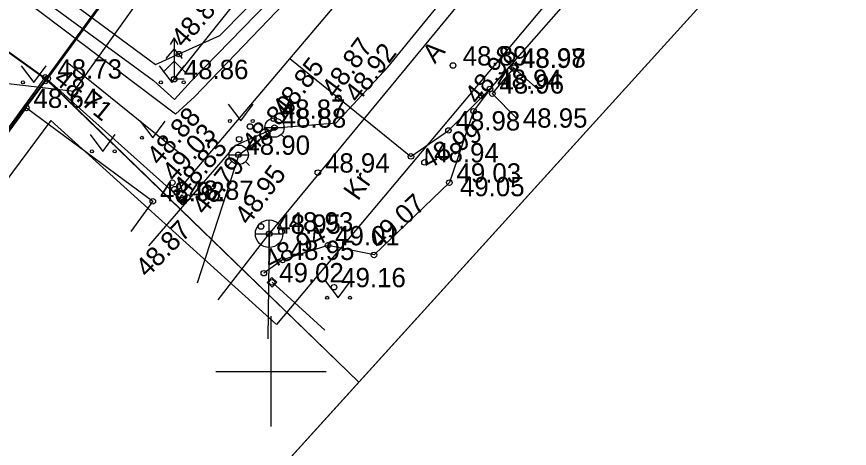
# Model space of a CAD drawing. Extents: x 640876 to 641418, y 6455595 to 6456085.
# Drawn here: x 641190.78 to 641220.97, y 6455847.21 to 6455862.86 of the extents above; entities that cross this region are included whole.
import ezdxf

# ---------------------------------------------------------------- set-up
doc = ezdxf.new("R2010")
doc.units = 0
for name, color, linetype in [('AED', 7, 'Continuous'), ('HALJASTUS', 7, 'Continuous'), ('HOONE', 7, 'Continuous'), ('KKAEV', 7, 'Continuous'), ('KORGUS', 7, 'Continuous'), ('KTRASS', 7, 'Continuous'), ('MOOTKORG', 7, 'Continuous'), ('MOOTMPUNKT', 7, 'Continuous'), ('MOOTPIIR', 7, 'Continuous'), ('PIIR', 7, 'Continuous'), ('PUU', 7, 'Continuous'), ('SITRASS', 7, 'Continuous'), ('TEE', 7, 'Continuous'), ('TTRASS', 7, 'Continuous'), ('VKAEV', 7, 'Continuous'), ('VORK', 7, 'Continuous'), ('VTRASS', 7, 'Continuous')]:
    doc.layers.add(name, color=color, linetype=linetype)

msp = doc.modelspace()

# ---------------------------------------------------------------- linework, layer by layer
at = {"layer": 'AED'}
for p, q in [((641208.634, 6455861.003), (641208.798, 6455861.191)), ((641208.798, 6455861.191), (641208.986, 6455861.027)), ((641208.634, 6455861.003), (641208.822, 6455860.839)), ((641208.822, 6455860.839), (641208.986, 6455861.027)), ((641196.764, 6455856.398), (641196.596, 6455856.212)), ((641196.596, 6455856.212), (641196.782, 6455856.044)), ((641196.764, 6455856.398), (641196.95, 6455856.23)), ((641196.95, 6455856.23), (641196.782, 6455856.044)), ((641200.03, 6455853.406), (641199.862, 6455853.22)), ((641199.862, 6455853.22), (641200.048, 6455853.052)), ((641200.03, 6455853.406), (641200.216, 6455853.238)), ((641200.216, 6455853.238), (641200.048, 6455853.052))]:
    msp.add_line(p, q, dxfattribs=at)
for points in [[(641208.8, 6455861.001), (641208.024, 6455860.071), (641208.909, 6455859.17)], [(641190.933, 6455807.239), (641184.916, 6455813.051), (641177.832, 6455819.82), (641173.204, 6455824.372), (641168.374, 6455829.07), (641172.424, 6455834.304), (641178.267, 6455842.112), (641182.222, 6455847.378), (641186.037, 6455852.714), (641191.816, 6455860.659), (641196.772, 6455856.219)], [(641201.952, 6455851.499), (641200.039, 6455853.229)]]:
    msp.add_lwpolyline(points, dxfattribs=at)
at = {"layer": 'HALJASTUS'}
for p, q in [((641190.945, 6455861.083), (641191.409, 6455860.477)), ((641191.409, 6455860.477), (641191.854, 6455861.083)), ((641195.945, 6455861.083), (641196.409, 6455860.477)), ((641196.409, 6455860.477), (641196.854, 6455861.083)), ((641198.448, 6455859.685), (641198.911, 6455859.078)), ((641198.911, 6455859.078), (641199.357, 6455859.685)), ((641195.26, 6455859.075), (641195.723, 6455858.468)), ((641195.723, 6455858.468), (641196.169, 6455859.075)), ((641193.445, 6455858.583), (641193.909, 6455857.977)), ((641193.909, 6455857.977), (641194.354, 6455858.583)), ((641201.976, 6455853.277), (641202.439, 6455852.67)), ((641202.439, 6455852.67), (641202.885, 6455853.277))]:
    msp.add_line(p, q, dxfattribs=at)
for centre in [(641191.008, 6455860.477), (641191.836, 6455860.477), (641196.008, 6455860.477), (641196.836, 6455860.477), (641198.51, 6455859.078), (641199.339, 6455859.078), (641195.322, 6455858.468), (641196.151, 6455858.468), (641193.508, 6455857.977), (641194.336, 6455857.977), (641202.038, 6455852.67), (641202.867, 6455852.67)]:
    msp.add_circle(centre, 0.055, dxfattribs=at)
at = {"layer": 'HOONE'}
msp.add_lwpolyline([(641179.081, 6455843.151), (641182.222, 6455847.378), (641191.132, 6455859.552), (641195.718, 6455856.166), (641194.92, 6455855.074)], dxfattribs=at)
msp.add_lwpolyline([(641179.081, 6455843.151), (641182.222, 6455847.378), (641191.132, 6455859.552), (641195.718, 6455856.166), (641194.92, 6455855.074)], dxfattribs=at)
at = {"layer": 'KKAEV'}
for p, q in [((641199.934, 6455854.49), (641199.934, 6455855.49)), ((641199.434, 6455854.99), (641200.434, 6455854.99))]:
    msp.add_line(p, q, dxfattribs=at)
msp.add_circle((641199.934, 6455854.99), 0.5, dxfattribs=at)
at = {"layer": 'KORGUS'}
for centre in [(641196.669, 6455861.503), (641206.602, 6455861.089), (641191.816, 6455860.659), (641191.907, 6455860.615), (641196.491, 6455860.595), (641202.442, 6455859.92), (641202.446, 6455859.883), (641207.634, 6455859.984), (641207.347, 6455859.432), (641199.241, 6455858.879), (641198.849, 6455858.417), (641205.074, 6455857.794), (641205.567, 6455857.577), (641201.699, 6455857.207), (641196.423, 6455856.841), (641196.5, 6455856.609), (641196.58, 6455856.487), (641196.837, 6455856.159), (641196.975, 6455856.303), (641199.641, 6455855.252), (641203.737, 6455854.222), (641199.742, 6455853.559)]:
    msp.add_circle(centre, 0.1, dxfattribs=at)
at = {"layer": 'KTRASS'}
for p, q in [((641198.081, 6455852.597), (641199.934, 6455854.99)), ((641199.934, 6455854.99), (641199.89, 6455851.179))]:
    msp.add_line(p, q, dxfattribs=at)
msp.add_lwpolyline([(641199.925, 6455854.961), (641212.81, 6455870.593), (641213.851, 6455869.715), (641214.751, 6455868.557), (641215.062, 6455868.275), (641216.191, 6455867.2)], dxfattribs=at)
at = {"layer": 'MOOTMPUNKT'}
for centre in [(641208.81, 6455861.015), (641207.942, 6455860.242), (641208.024, 6455860.071), (641191.132, 6455859.552), (641200.098, 6455859.158), (641200.128, 6455858.837), (641206.434, 6455858.735), (641198.814, 6455857.853), (641206.467, 6455856.844), (641195.718, 6455856.166), (641196.772, 6455856.219), (641199.934, 6455854.99), (641200.381, 6455855.071), (641202.067, 6455854.57), (641200.424, 6455854.039), (641200.039, 6455853.229), (641202.287, 6455853.052)]:
    msp.add_circle(centre, 0.1, dxfattribs=at)
at = {"layer": 'MOOTPIIR'}
msp.add_lwpolyline([(641060.916, 6455895.936), (641100.061, 6455950.482), (641099.586, 6455952.159), (641069.132, 6455984.035), (641066.132, 6455988.623), (641076.463, 6456005.049), (641230.642, 6456010.048), (641237.36, 6455995.24), (641237.24, 6455992.81), (641236.258, 6455990.888), (641229.041, 6455971.315), (641203.026, 6455909.57), (641225.257, 6455906.847), (641239.512, 6455898.491), (641200.195, 6455851.697), (641192.016, 6455859.099), (641169.785, 6455829.138), (641192.025, 6455807.568), (641252.96, 6455758.075), (641231.388, 6455736.74), (641191.474, 6455775.975), (641152.419, 6455787.914), (641136.351, 6455788.307), (641049.066, 6455856.043)], dxfattribs=at)
at = {"layer": 'PIIR'}
for points in [[(641222.58, 6455998.61), (641237.36, 6455995.24), (641235.34, 6455991.29), (641228.11, 6455971.68), (641220.5, 6455953.19), (641213.41, 6455936.25), (641201.58, 6455908.74), (641224.93, 6455905.88), (641191.87, 6455860.58), (641157.02, 6455885.66), (641160.91, 6455891.99), (641102.26, 6455951.82), (641074.95, 6455979.64), (641084.84, 6455991.92)], [(641216.67, 6455752.61), (641192, 6455776.86), (641152.58, 6455788.91), (641136.9, 6455789.33), (641119.28, 6455802.72), (641101.72, 6455816.27), (641098.61, 6455818.83), (641124.03, 6455849.78), (641139.51, 6455868.99), (641157, 6455885.69), (641191.84, 6455860.59), (641168.46, 6455829.03), (641191.37, 6455806.79), (641234.69, 6455771.62)], [(641224.6, 6455873.24), (641239.42, 6455859.81), (641199.12, 6455815.36), (641184.3, 6455828.79)], [(641184.3, 6455828.79), (641199.12, 6455815.36), (641191.36, 6455806.82), (641168.47, 6455829), (641191.87, 6455860.58), (641203.18, 6455849.61)]]:
    msp.add_lwpolyline(points, close=True, dxfattribs=at)
msp.add_lwpolyline([(641315.35, 6455858.84), (641292.55, 6455879.89), (641262.53, 6455885.29), (641239.33, 6455889.47), (641203.18, 6455849.61), (641191.84, 6455860.59), (641224.93, 6455905.88), (641249.88, 6455902.84), (641270.69, 6455899.15), (641280.77, 6455915.37), (641291.33, 6455932.26), (641301.94, 6455948.72)], dxfattribs=at)
at = {"layer": 'PUU'}
for p, q in [((641196.491, 6455862.095), (641196.341, 6455861.845)), ((641196.641, 6455861.845), (641196.491, 6455862.095)), ((641196.491, 6455862.095), (641196.491, 6455860.595)), ((641196.491, 6455861.695), (641196.191, 6455861.345)), ((641196.791, 6455861.345), (641196.491, 6455861.695)), ((641196.491, 6455861.245), (641196.091, 6455860.845)), ((641196.891, 6455860.845), (641196.491, 6455861.245)), ((641196.851, 6455860.595), (641196.491, 6455860.595))]:
    msp.add_line(p, q, dxfattribs=at)
for points in [[(641196.491, 6455860.595), (641211.119, 6455878.92)], [(641196.751, 6455857.846), (641192.554, 6455861.247)]]:
    msp.add_lwpolyline(points, dxfattribs=at)
at = {"layer": 'SITRASS'}
for points in [[(641160.717, 6455890.02), (641160.061, 6455889.202), (641160.124, 6455887.433), (641162.714, 6455885.215), (641168.31, 6455881.226), (641178.228, 6455873.851), (641188.611, 6455866.439), (641195.817, 6455861.122), (641198.143, 6455862.18), (641205.423, 6455869.555), (641212.959, 6455877.434), (641219.89, 6455884.166), (641222.806, 6455887.129), (641228.363, 6455892.82), (641230.103, 6455894.633)], [(641174.28, 6455868.6), (641175.337, 6455869.665), (641176.394, 6455870.73), (641176.446, 6455870.679), (641190.159, 6455860.476), (641192.86, 6455860.157), (641202.953, 6455874.327), (641207.15, 6455874.999), (641212.959, 6455877.434)]]:
    msp.add_lwpolyline(points, dxfattribs=at)
at = {"layer": 'TEE'}
for points in [[(641196.58, 6455856.487), (641202.972, 6455864.043), (641209.127, 6455871.296), (641214.674, 6455877.825), (641214.783, 6455878.584), (641214.589, 6455879.582), (641214.19, 6455880.14), (641208.972, 6455884.583), (641206.409, 6455886.654)], [(641207.942, 6455860.242), (641211.935, 6455864.789), (641216.758, 6455870.138), (641221.631, 6455875.683)], [(641200.685, 6455861.339), (641205.074, 6455857.794), (641206.434, 6455858.735), (641207.942, 6455860.242)], [(641208.758, 6455861.042), (641209.788, 6455860.14)], [(641207.942, 6455860.242), (641207.347, 6455859.432), (641206.467, 6455856.844), (641203.737, 6455854.222), (641202.067, 6455854.57), (641200.424, 6455854.039), (641199.742, 6455853.559)]]:
    msp.add_lwpolyline(points, dxfattribs=at)
at = {"layer": 'TTRASS'}
for points in [[(641146.983, 6455877.597), (641147.637, 6455878.312), (641148.076, 6455878.791), (641148.587, 6455879.349), (641156.827, 6455888.351), (641157.502, 6455889.088), (641158.299, 6455888.492), (641167.659, 6455881.582), (641177.2, 6455874.303), (641186.795, 6455867.097), (641195.745, 6455860.541), (641196.509, 6455859.853), (641197.119, 6455860.535), (641205.5, 6455869.137), (641213.939, 6455877.707), (641222.42, 6455886.169), (641230.878, 6455894.702), (641235.947, 6455899.687), (641236.146, 6455899.925), (641236.328, 6455899.987), (641239.542, 6455899.756)], [(641240.141, 6455899.285), (641236.489, 6455899.529), (641236.348, 6455899.464), (641230.948, 6455894.114), (641222.434, 6455885.667), (641213.976, 6455877.157), (641205.539, 6455868.624), (641197.23, 6455859.957), (641196.541, 6455859.328), (641186.928, 6455866.582), (641177.306, 6455873.752), (641167.696, 6455880.94), (641158.359, 6455887.923), (641157.562, 6455888.52), (641156.887, 6455887.782), (641148.647, 6455878.781), (641148.136, 6455878.223), (641147.697, 6455877.743), (641147.022, 6455877.006)]]:
    msp.add_lwpolyline(points, dxfattribs=at)
at = {"layer": 'VKAEV'}
for p, q in [((641199.778, 6455858.837), (641200.478, 6455858.837)), ((641199.881, 6455858.59), (641199.741, 6455858.45)), ((641200.375, 6455858.59), (641200.515, 6455858.45)), ((641198.483, 6455857.853), (641199.183, 6455857.853)), ((641198.586, 6455857.606), (641198.446, 6455857.466)), ((641199.08, 6455857.606), (641199.22, 6455857.466))]:
    msp.add_line(p, q, dxfattribs=at)
for centre in [(641200.128, 6455858.837), (641198.833, 6455857.853)]:
    msp.add_circle(centre, 0.35, dxfattribs=at)
at = {"layer": 'VORK'}
for p, q in [((641200, 6455852), (641200, 6455848)), ((641198, 6455850), (641202, 6455850))]:
    msp.add_line(p, q, dxfattribs=at)
at = {"layer": 'VTRASS'}
for points in [[(641198.833, 6455857.853), (641200.156, 6455858.831), (641202.364, 6455859.006), (641204.234, 6455861.028), (641213.817, 6455872.768), (641216.691, 6455870.253)], [(641195.578, 6455854.558), (641198.722, 6455858.197), (641200.156, 6455858.831)], [(641195.578, 6455854.558), (641198.722, 6455858.197)], [(641198.833, 6455857.853), (641197.319, 6455853.194)]]:
    msp.add_lwpolyline(points, dxfattribs=at)

# ---------------------------------------------------------------- texts
at = {"layer": 'KORGUS'}
for s, rotation, p in [(' 48.84', 48.9689, (641196.669, 6455861.503)), ('48.87', 53.6778, (641202.337, 6455859.87)), (' 48.92', 52.1772, (641202.995, 6455859.491)), (' 48.98', 51.6818, (641207.347, 6455859.432)), (' 48.85', 52.6323, (641200.385, 6455858.966)), (' 48.71', 320.9078, (641191.878, 6455860.677)), ('48.80', 47.3095, (641199.389, 6455857.9)), ('48.88', 48.8552, (641195.957, 6455857.426)), ('49.03', 48.856, (641196.516, 6455856.837)), (' 48.99', 29.2446, (641205.457, 6455857.174)), ('48.83', 49.0876, (641196.92, 6455856.312)), ('48.79', 50.6748, (641197.597, 6455855.634)), (' 48.95', 53.5146, (641199.035, 6455855.057)), (' 49.07', 42.5482, (641203.737, 6455854.222)), (' 48.87', 45.8041, (641195.338, 6455853.182)), (' 48.94', 26.8876, (641199.742, 6455853.559))]:
    msp.add_text(s, height=0.7, rotation=rotation, dxfattribs=at).set_placement(p)
for s, p in [('48.89', (641206.952, 6455861.089)), ('48.73', (641192.257, 6455860.615)), ('48.86', (641196.841, 6455860.595)), (' 48.95', (641208.873, 6455858.837)), ('48.94', (641205.917, 6455857.577)), (' 48.94', (641201.699, 6455857.207))]:
    msp.add_text(s, height=0.7, dxfattribs=at).set_placement(p)
at = {"layer": 'MOOTKORG'}
for s, p in [(' 48.97', (641208.8, 6455861.001)), (' 48.98', (641208.81, 6455861.015)), (' 48.94', (641207.942, 6455860.242)), (' 48.96', (641208.024, 6455860.071)), (' 48.64', (641191.132, 6455859.552)), (' 48.87', (641200.098, 6455859.158)), (' 48.88', (641200.128, 6455858.837)), (' 48.98', (641206.434, 6455858.735)), (' 48.90', (641198.814, 6455857.853)), (' 49.03', (641206.467, 6455856.844)), (' 48.92', (641195.718, 6455856.166)), (' 48.87', (641196.772, 6455856.219)), (' 49.05', (641206.592, 6455856.35)), (' 48.95', (641199.934, 6455854.99)), (' 48.93', (641200.381, 6455855.071)), (' 49.01', (641202.067, 6455854.57)), (' 48.95', (641200.424, 6455854.039)), (' 49.02', (641200.039, 6455853.229)), (' 49.16', (641202.287, 6455853.052))]:
    msp.add_text(s, height=0.7, dxfattribs=at).set_placement(p)
at = {"layer": 'TEE'}
for s, rotation, p in [('A', 48.485, (641205.942, 6455861.125)), ('Kr', 54.9374, (641203.152, 6455856.152))]:
    msp.add_text(s, height=0.7, rotation=rotation, dxfattribs=at).set_placement(p)

doc.saveas('drawing.dxf')
